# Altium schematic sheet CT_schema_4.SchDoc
size 226 x 258 mm
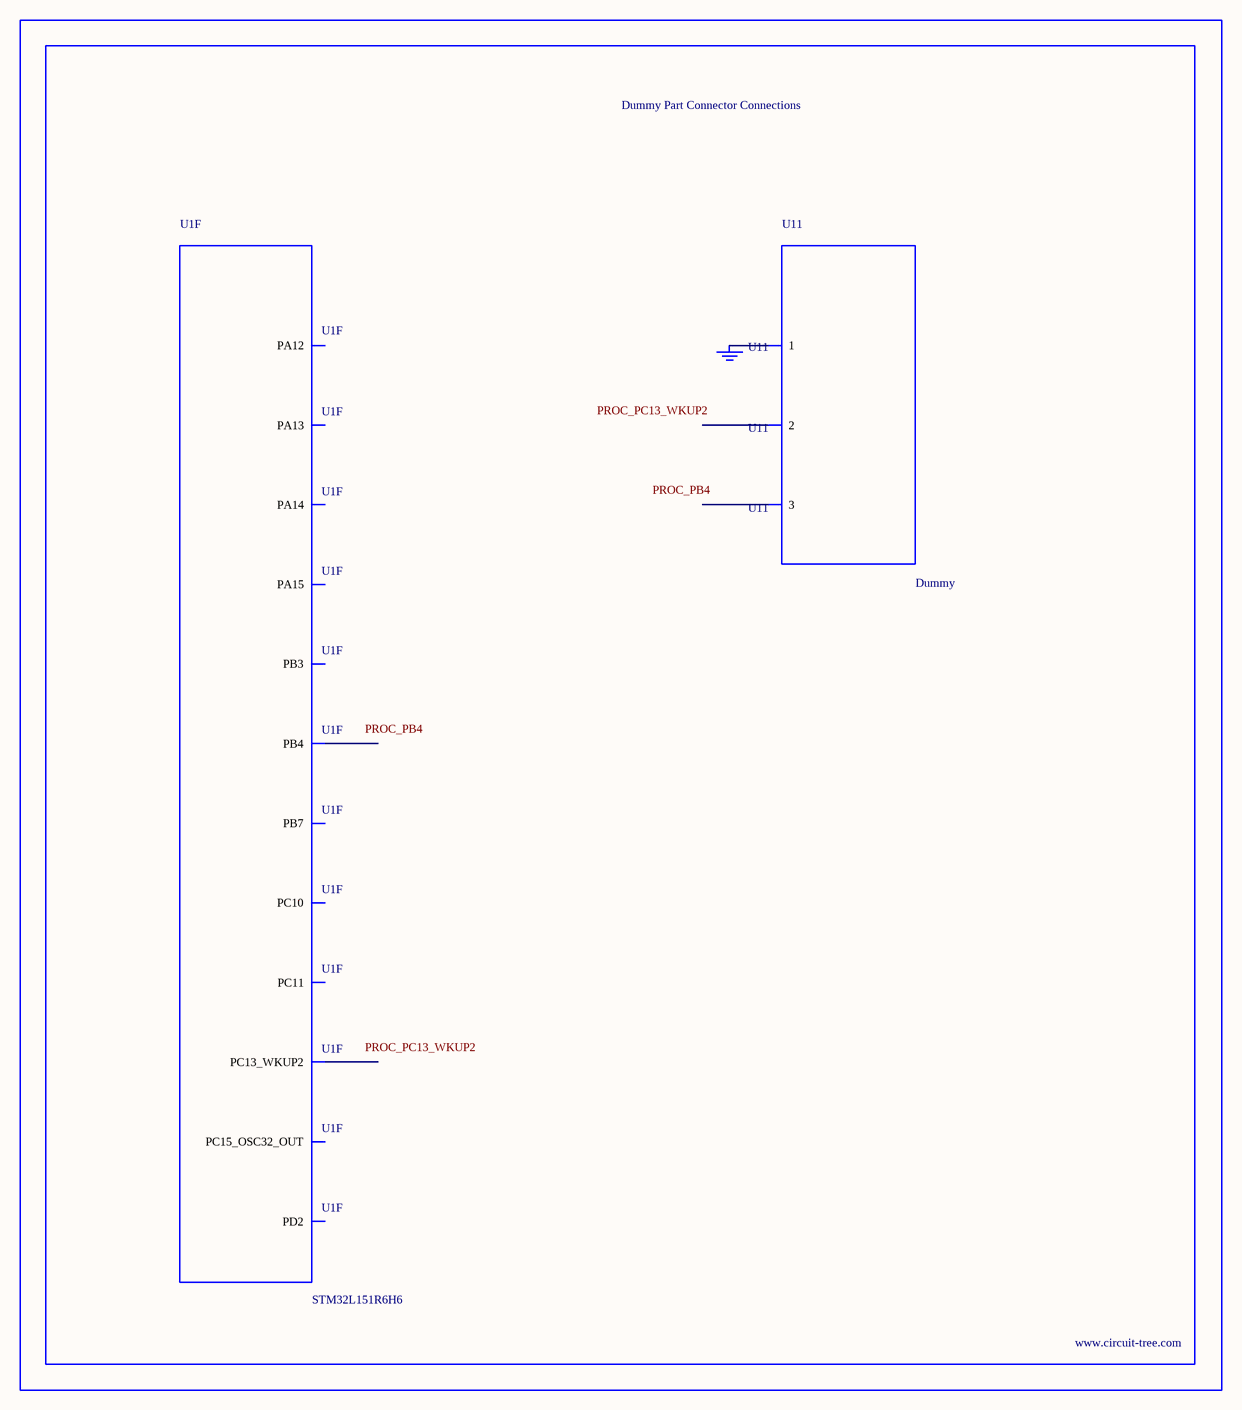
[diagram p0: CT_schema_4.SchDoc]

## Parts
BORDER3  (no value)
GND_INSTANCE_3_0  (no value)
U1  STM32L151R6H6  [TFBGA64]  (part F of 6)
U11  Dummy  [DUMMY_PACKAGE_110]

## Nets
NetGND_INSTANCE_3_0_0: GND_INSTANCE_3_0.0(GND) U11.1

Not connected (* = marked no-connect by the designer): U1 A2(PC13_WKUP2) A4(PB4) A5(PB3) A6(PA15) A7(PA14) A8(PA13) B1(PC15_OSC32_OUT) B5(PD2) B6(PC11) B7(PC10) B8(PA12) C3(PB7); U11 2 3

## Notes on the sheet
- Labels drawn without touching a wire or pin: PROC_PB4, PROC_PC13_WKUP2

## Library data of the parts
BORDER3 = BORDER_PAGE3
GND_INSTANCE_3_0 = GND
